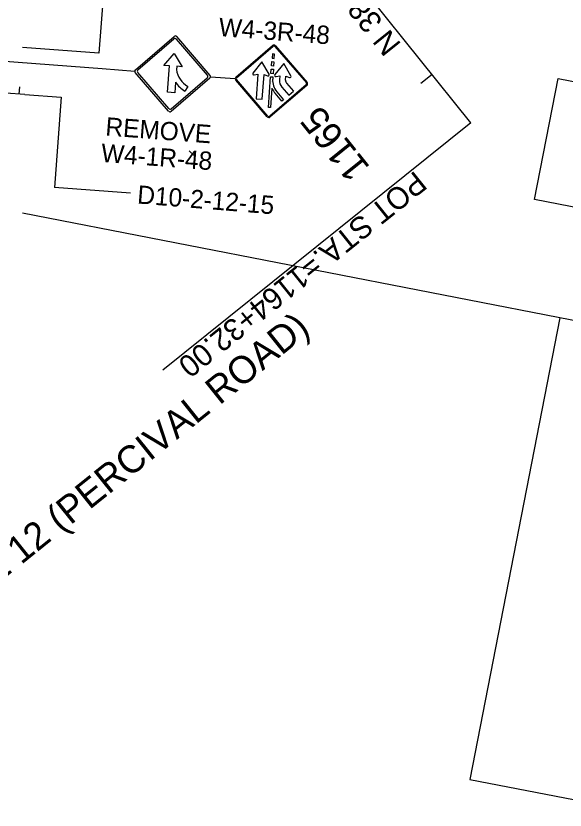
# Model space of a CAD drawing. Extents: x 2001876 to 2025694, y 804561 to 868938.
# Drawn here: x 2023436 to 2024038, y 806985 to 807854 of the extents above; entities that cross this region are included whole.
import ezdxf

# ---------------------------------------------------------------- set-up
doc = ezdxf.new("R2010")
doc.units = 0
for name, color, linetype in [('RD_HC_CL_Rel', 7, 'Continuous'), ('RD_HC_Data_Rel', 7, 'Continuous'), ('RD_HC_Data_Tic_Rel', 7, 'Continuous'), ('RD_HC_TX_Rel_Sta50', 7, 'Continuous'), ('RD_Sketch2', 7, 'Continuous'), ('RD_TX_RoadID', 7, 'Continuous'), ('TR SN EXTRUDED PANEL SIGNS - GROUND MOUNTED', 7, 'Continuous'), ('TR SN EXTRUDED PANEL SIGNS- MOUNTED OVERHEAD', 7, 'Continuous'), ('TR SN FLAT SHEET - TYPE III - FIXED SZ and MSG SIGN', 7, 'Continuous')]:
    doc.layers.add(name, color=color, linetype=linetype)

msp = doc.modelspace()

# ---------------------------------------------------------------- linework, layer by layer
at = {"layer": 'RD_HC_CL_Rel'}
msp.add_line((2023934.58, 807736.81), (2023655.68, 808084.23), dxfattribs=at)
at = {"layer": 'RD_HC_Data_Rel'}
msp.add_line((2023934.58, 807736.81), (2023597.18, 807465.96), dxfattribs=at)
at = {"layer": 'RD_HC_Data_Tic_Rel'}
msp.add_line((2023892.01, 807789.84), (2023879.53, 807779.82), dxfattribs=at)
at = {"layer": 'RD_Sketch2'}
msp.add_line((2023625.77, 807706.11), (2023631.75, 807700.79), dxfattribs=at)
at = {"layer": 'TR SN EXTRUDED PANEL SIGNS - GROUND MOUNTED'}
for p, q in [((2023576.3, 808483.89), (2023527.15, 807813.14)), ((2023527.15, 807813.14), (2023443.43, 807819.41)), ((2023419.15, 807804.55), (2023530.83, 807796.18)), ((2023530.83, 807796.18), (2023566.3, 807793.52)), ((2023649.27, 807787.31), (2023676.41, 807785.27)), ((2023446.07, 807767.72), (2023425.27, 807769.29)), ((2023439.84, 807768.19), (2023440.44, 807776.15)), ((2023446.07, 807767.72), (2023485.79, 807764.72)), ((2023485.79, 807764.72), (2023478.4, 807666.14)), ((2023561.71, 807659.9), (2023478.4, 807666.14))]:
    msp.add_line(p, q, dxfattribs=at)
at = {"layer": 'TR SN EXTRUDED PANEL SIGNS- MOUNTED OVERHEAD'}
for p, q in [((2024200.9, 807490.6), (2023443.5, 807638)), ((2024031.81, 807523.51), (2023933.47, 807018.17)), ((2023933.47, 807018.17), (2024105.97, 806984.59))]:
    msp.add_line(p, q, dxfattribs=at)
msp.add_lwpolyline([(2024029.97, 807785.38), (2024780.7, 807639.28), (2024754.92, 807506.8), (2024004.19, 807652.9)], close=True, dxfattribs=at)
at = {"layer": 'TR SN FLAT SHEET - TYPE III - FIXED SZ and MSG SIGN'}
for p, q in [((2023566.99, 807794.89), (2023609.44, 807831.42)), ((2023648.79, 807788.76), (2023612.26, 807831.21)), ((2023569.81, 807794.68), (2023609.23, 807828.6)), ((2023645.97, 807788.97), (2023612.05, 807828.39)), ((2023677.23, 807786.91), (2023717.26, 807821.35)), ((2023677.86, 807786.18), (2023717.88, 807820.62)), ((2023720.64, 807821.1), (2023755.08, 807781.07)), ((2023598.35, 807799.74), (2023609.35, 807812.76)), ((2023609.35, 807812.76), (2023618.29, 807798.25)), ((2023717.08, 807812.31), (2023716.72, 807807.52)), ((2023719.47, 807812.13), (2023717.08, 807812.31)), ((2023719.11, 807807.34), (2023719.47, 807812.13)), ((2023719.91, 807820.47), (2023754.35, 807780.45)), ((2023705.59, 807803.54), (2023695.8, 807791.34)), ((2023713.45, 807790.02), (2023705.59, 807803.54)), ((2023716.09, 807799.14), (2023716.45, 807803.93)), ((2023716.45, 807803.93), (2023718.84, 807803.75)), ((2023716.72, 807807.52), (2023719.11, 807807.34)), ((2023718.84, 807803.75), (2023718.48, 807798.96)), ((2023604.33, 807799.3), (2023598.35, 807799.74)), ((2023602.16, 807770.33), (2023604.33, 807799.3)), ((2023612.31, 807798.7), (2023612.03, 807795)), ((2023618.29, 807798.25), (2023612.31, 807798.7)), ((2023715.46, 807790.77), (2023715.82, 807795.55)), ((2023715.82, 807795.55), (2023718.21, 807795.37)), ((2023718.48, 807798.96), (2023716.09, 807799.14)), ((2023718.21, 807795.37), (2023717.86, 807790.59)), ((2023729.52, 807801.75), (2023719.74, 807789.55)), ((2023737.38, 807788.22), (2023729.52, 807801.75)), ((2023603.31, 807749.62), (2023566.78, 807792.07)), ((2023603.52, 807752.44), (2023569.6, 807791.86)), ((2023606.13, 807749.41), (2023648.58, 807785.94)), ((2023606.34, 807752.23), (2023645.76, 807786.15)), ((2023697.16, 807789.2), (2023701.22, 807790.16)), ((2023701.22, 807790.16), (2023699.19, 807763.11)), ((2023705.89, 807762.6), (2023707.92, 807789.66)), ((2023707.92, 807789.66), (2023711.78, 807788.11)), ((2023712.68, 807753.67), (2023715.19, 807787.18)), ((2023715.19, 807787.18), (2023717.59, 807787)), ((2023717.86, 807790.59), (2023715.46, 807790.77)), ((2023717.59, 807787), (2023717.41, 807784.6)), ((2023721.1, 807787.41), (2023725.15, 807788.37)), ((2023725.15, 807788.37), (2023724.83, 807784.05)), ((2023731.53, 807783.55), (2023731.85, 807787.87)), ((2023731.85, 807787.87), (2023735.72, 807786.31)), ((2023611, 807781.27), (2023610.14, 807769.73)), ((2023711.42, 807743.5), (2023676.98, 807783.53)), ((2023712.15, 807744.13), (2023677.71, 807784.15)), ((2023754.2, 807778.42), (2023714.18, 807743.98)), ((2023754.83, 807777.69), (2023714.81, 807743.25)), ((2023716.03, 807782.3), (2023716.03, 807782.3)), ((2023732.68, 807780.06), (2023740.14, 807771.38)), ((2023610.14, 807769.73), (2023602.16, 807770.33)), ((2023624.36, 807776.75), (2023621.35, 807771.55)), ((2023716.67, 807774.79), (2023715.07, 807753.49)), ((2023727.59, 807760.58), (2023720.12, 807769.25)), ((2023721.94, 807770.82), (2023729.41, 807762.15)), ((2023727.58, 807775.67), (2023735.04, 807767)), ((2023735.04, 807767), (2023740.14, 807771.38)), ((2023699.19, 807763.11), (2023705.89, 807762.6)), ((2023729.41, 807762.15), (2023727.59, 807760.58)), ((2023715.07, 807753.49), (2023712.68, 807753.67))]:
    msp.add_line(p, q, dxfattribs=at)
for centre, radius, start, end in [((2023610.74, 807829.9), 2, 40.71386, 130.71295), ((2023610.53, 807827.08), 2, 40.71434, 130.71295), ((2023718.82, 807819.53), 2.4, 40.71296, 130.71296), ((2023718.82, 807819.53), 2.4, 40.71296, 130.71296), ((2023718.82, 807819.53), 1.44, 40.71296, 130.71296), ((2023568.3, 807793.37), 2, 130.71295, 220.71374), ((2023571.12, 807793.16), 2, 130.71295, 220.71584), ((2023636.93, 807798.53), 25.15, 188.06113, 239.99414), ((2023644.45, 807787.67), 2, 310.71296, 40.71083), ((2023647.27, 807787.45), 2, 310.71296, 40.70864), ((2023678.8, 807785.09), 2.4, 130.71296, 220.71296), ((2023678.8, 807785.09), 2.4, 130.71296, 220.71296), ((2023678.8, 807785.09), 1.44, 130.71296, 220.71296), ((2023696.86, 807790.51), 1.34, 140.44039, 283.75904), ((2023712.28, 807789.36), 1.34, 247.66687, 30.98552), ((2023720.8, 807788.72), 1.34, 140.44039, 283.75904), ((2023736.21, 807787.56), 1.34, 247.66687, 30.98552), ((2023636.93, 807798.53), 31.15, 213.64866, 239.99414), ((2023736.31, 807783.19), 18.96, 175.71314, 220.71296), ((2023736.31, 807783.19), 11.52, 175.71296, 220.71296), ((2023736.31, 807783.19), 4.8, 175.7135, 220.71296), ((2023753.26, 807779.51), 1.44, 310.71296, 40.71296), ((2023753.26, 807779.51), 2.4, 310.71296, 40.71296), ((2023753.26, 807779.51), 2.4, 310.71296, 40.71296), ((2023736.31, 807783.19), 21.36, 203.13473, 220.71296), ((2023605.04, 807753.75), 2, 220.71133, 310.71143), ((2023604.82, 807750.93), 2, 220.71295, 310.71294), ((2023713.24, 807745.07), 2.4, 220.71296, 310.71296), ((2023713.24, 807745.07), 2.4, 220.71296, 310.71296), ((2023713.24, 807745.07), 1.44, 220.71296, 310.71296)]:
    msp.add_arc(centre, radius, start, end, dxfattribs=at)

# ---------------------------------------------------------------- texts
at = {"layer": 'RD_HC_Data_Rel'}
for s, rotation, p in [('N 38%%d 45\' 20" W', 128.75568, (2023858.99, 807822.7)), ('POT STA.=1164+32.00', 218.75568, (2023873.44, 807685.17))]:
    msp.add_text(s, height=24, rotation=rotation, dxfattribs=at).set_placement(p)
at = {"layer": 'RD_HC_TX_Rel_Sta50'}
msp.add_text('1165', height=30, rotation=128.75568, dxfattribs=at).set_placement((2023824.94, 807688.08))
at = {"layer": 'RD_TX_RoadID'}
msp.add_text('S.C. ROUTE 12 (PERCIVAL ROAD)', height=30, rotation=38.77203, dxfattribs=at).set_placement((2023254.23, 807101.97))
at = {"layer": 'TR SN EXTRUDED PANEL SIGNS - GROUND MOUNTED'}
for s, p in [('W4-3R-48', (2023657.77, 807831.86)), ('REMOVE', (2023533.74, 807723.05)), ('W4-1R-48', (2023528.9, 807694.12))]:
    msp.add_text(s, height=20, rotation=355.68749, dxfattribs=at).set_placement(p)
at = {"layer": 'TR SN EXTRUDED PANEL SIGNS- MOUNTED OVERHEAD'}
msp.add_text('D10-2-12-15', height=20, rotation=355.43909, dxfattribs=at).set_placement((2023568.57, 807648.58))

doc.saveas('drawing.dxf')
